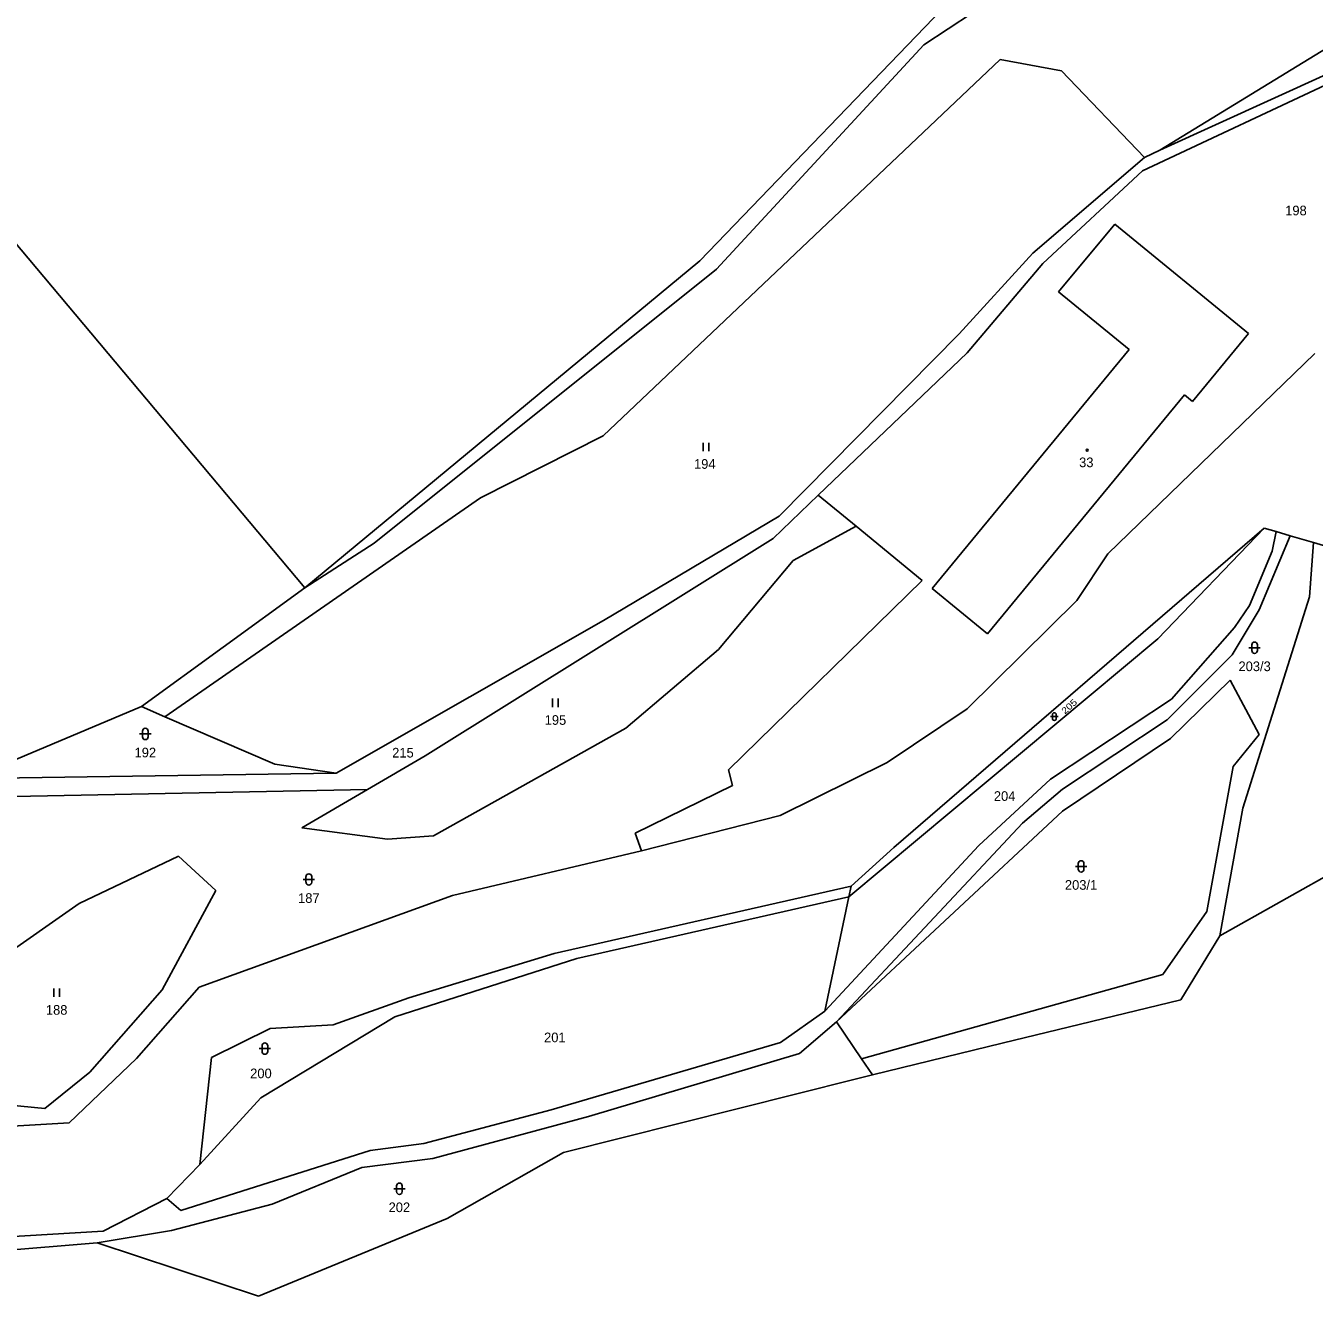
# Model space of a CAD drawing. Extents: x -601877 to -599786, y -1122905 to -1121218.
# Drawn here: x -600206.4 to -599979.4, y -1122461.1 to -1122237.3 of the extents above; entities that cross this region are included whole.
import ezdxf
from ezdxf.enums import TextEntityAlignment as Align

# ---------------------------------------------------------------- set-up
doc = ezdxf.new("R2010")
doc.units = 0
doc.header["$LTSCALE"] = 0.68
for name, color, linetype, lineweight in [('1', 7, 'Continuous', 25), ('3', 7, 'Continuous', 25), ('5', 7, 'Continuous', 25)]:
    doc.layers.add(name, color=color, linetype=linetype, lineweight=lineweight)
doc.layers.add('2', color=7, linetype='Continuous')

msp = doc.modelspace()

# ---------------------------------------------------------------- linework, layer by layer
at = {"layer": '1'}
for p, q in [((-600006.61, -1122259.26), (-599955.88, -1122228.15)), ((-600031.07, -1122229.36), (-600048.16, -1122240.69)), ((-600087.63, -1122278.73), (-600043.41, -1122232.83)), ((-600048.16, -1122240.69), (-600084.7, -1122280.19)), ((-600104.71, -1122309.54), (-600034.71, -1122243.27)), ((-600023.95, -1122245.28), (-600034.71, -1122243.27)), ((-600009.33, -1122260.51), (-600023.95, -1122245.28)), ((-599976.54, -1122245.54), (-600006.61, -1122259.26)), ((-599974.57, -1122246.46), (-600009.65, -1122262.88)), ((-600229.43, -1122250.39), (-600157.25, -1122336.33)), ((-600006.61, -1122259.26), (-600009.33, -1122260.51)), ((-600028.97, -1122277.36), (-600009.33, -1122260.51)), ((-600009.65, -1122262.88), (-600027.23, -1122279.19)), ((-600024.44, -1122284.22), (-600014.52, -1122272.3)), ((-600014.52, -1122272.3), (-599990.99, -1122291.56)), ((-600041.94, -1122291.62), (-600028.97, -1122277.36)), ((-600157.25, -1122336.33), (-600087.63, -1122278.73)), ((-600084.7, -1122280.19), (-600145.01, -1122328.47)), ((-600040.57, -1122294.91), (-600027.23, -1122279.19)), ((-600011.99, -1122294.36), (-600024.44, -1122284.22)), ((-600073.65, -1122323.71), (-600041.94, -1122291.62)), ((-599990.99, -1122291.56), (-600000.86, -1122303.54)), ((-600066.8, -1122320.02), (-600040.57, -1122294.91)), ((-600046.7, -1122336.48), (-600011.99, -1122294.36)), ((-599979.3, -1122295.06), (-600015.75, -1122330.35)), ((-600002.25, -1122302.34), (-600036.98, -1122344.44)), ((-600000.86, -1122303.54), (-600002.25, -1122302.34)), ((-600126.28, -1122320.51), (-600104.71, -1122309.54)), ((-600181.91, -1122359.05), (-600126.28, -1122320.51)), ((-600074.75, -1122327.64), (-600066.8, -1122320.02)), ((-600060.12, -1122325.49), (-600066.8, -1122320.02)), ((-600104.62, -1122342.09), (-600073.65, -1122323.71)), ((-600071.18, -1122331.55), (-600060.12, -1122325.49)), ((-600048.46, -1122335.04), (-600060.12, -1122325.49)), ((-600053.48, -1122382.07), (-599988.25, -1122325.82)), ((-599988.25, -1122325.82), (-600006.95, -1122345.31)), ((-599986.13, -1122326.44), (-599988.25, -1122325.82)), ((-600074.75, -1122327.64), (-600136.02, -1122365.94)), ((-599989.13, -1122340.24), (-599983.63, -1122327.17)), ((-599986.82, -1122329.9), (-599986.13, -1122326.44)), ((-599983.63, -1122327.17), (-599986.13, -1122326.44)), ((-599979.5, -1122328.38), (-599983.63, -1122327.17)), ((-600145.01, -1122328.47), (-600157.25, -1122336.33)), ((-600015.75, -1122330.35), (-600021.22, -1122338.56)), ((-599990.78, -1122339.47), (-599986.82, -1122329.9)), ((-599980.22, -1122337.93), (-599979.5, -1122328.38)), ((-599967.79, -1122331.82), (-599979.5, -1122328.38)), ((-600084.38, -1122347.18), (-600071.18, -1122331.55)), ((-600157.25, -1122336.33), (-600186.03, -1122357.27)), ((-600048.46, -1122335.04), (-600082.6, -1122368.42)), ((-600036.98, -1122344.44), (-600046.7, -1122336.48)), ((-600040.57, -1122357.63), (-600021.22, -1122338.56)), ((-599991.99, -1122375.13), (-599980.22, -1122337.93)), ((-599993.86, -1122348.17), (-599989.13, -1122340.24)), ((-599993.42, -1122343.32), (-599990.78, -1122339.47)), ((-600151.7, -1122368.97), (-600104.62, -1122342.09)), ((-600004.53, -1122355.98), (-599993.42, -1122343.32)), ((-600061.4, -1122390.77), (-600006.95, -1122345.31)), ((-600100.66, -1122361.04), (-600084.38, -1122347.18)), ((-600005.3, -1122359.61), (-599993.86, -1122348.17)), ((-600004.75, -1122362.86), (-599994.19, -1122352.62)), ((-599994.19, -1122352.62), (-599989.13, -1122362.15)), ((-600216.26, -1122369.96), (-600186.03, -1122357.27)), ((-600186.03, -1122357.27), (-600181.91, -1122359.05)), ((-600025.87, -1122370.07), (-600004.53, -1122355.98)), ((-600181.91, -1122359.05), (-600162.55, -1122367.41)), ((-600054.64, -1122367.14), (-600040.57, -1122357.63)), ((-600023.78, -1122371.83), (-600005.3, -1122359.61)), ((-600134.59, -1122380.03), (-600100.66, -1122361.04)), ((-599989.13, -1122362.15), (-599993.7, -1122367.81)), ((-600023.78, -1122375.68), (-600004.75, -1122362.86)), ((-600136.02, -1122365.94), (-600146.19, -1122371.89)), ((-600216.26, -1122369.96), (-600151.7, -1122368.97)), ((-600162.55, -1122367.41), (-600151.7, -1122368.97)), ((-600082.6, -1122368.42), (-600081.87, -1122371.16)), ((-600073.47, -1122376.47), (-600054.64, -1122367.14)), ((-599993.7, -1122367.81), (-599998.32, -1122393.35)), ((-600081.87, -1122371.16), (-600099.05, -1122379.57)), ((-600038.52, -1122381.74), (-600025.87, -1122370.07)), ((-600215.93, -1122373.26), (-600146.19, -1122371.89)), ((-600146.19, -1122371.89), (-600157.75, -1122378.65)), ((-600030.82, -1122377.77), (-600023.78, -1122371.83)), ((-600063.59, -1122412.77), (-600023.78, -1122375.68)), ((-599996.04, -1122397.64), (-599991.99, -1122375.13)), ((-600097.95, -1122382.68), (-600073.47, -1122376.47)), ((-600063.59, -1122412.77), (-600030.82, -1122377.77)), ((-600157.75, -1122378.65), (-600142.68, -1122380.64)), ((-600142.68, -1122380.64), (-600134.59, -1122380.03)), ((-600099.05, -1122379.57), (-600097.95, -1122382.68)), ((-600065.63, -1122410.9), (-600038.52, -1122381.74)), ((-600061.01, -1122388.89), (-600053.48, -1122382.07)), ((-600179.52, -1122383.61), (-600197.01, -1122391.97)), ((-600172.92, -1122389.66), (-600179.52, -1122383.61)), ((-600131.24, -1122390.54), (-600097.95, -1122382.68)), ((-599996.04, -1122397.64), (-599974.31, -1122385.44)), ((-600113.31, -1122400.78), (-600061.01, -1122388.89)), ((-600061.4, -1122390.77), (-600061.01, -1122388.89)), ((-600182.38, -1122407.16), (-600172.92, -1122389.66)), ((-600175.89, -1122406.72), (-600131.24, -1122390.54)), ((-600109.35, -1122401.66), (-600061.4, -1122390.77)), ((-600065.63, -1122410.9), (-600061.4, -1122390.77)), ((-600197.01, -1122391.97), (-600221.65, -1122409.14)), ((-599998.32, -1122393.35), (-600006.07, -1122404.46)), ((-600002.93, -1122408.92), (-599996.04, -1122397.64)), ((-600141.36, -1122411.89), (-600109.35, -1122401.66)), ((-600138.94, -1122408.59), (-600113.31, -1122400.78)), ((-600195.14, -1122421.69), (-600182.38, -1122407.16)), ((-600186.89, -1122419.27), (-600175.89, -1122406.72)), ((-600152.25, -1122413.32), (-600138.94, -1122408.59)), ((-600034.4, -1122416.58), (-600002.93, -1122408.92)), ((-600165, -1122426.2), (-600141.36, -1122411.89)), ((-600073.44, -1122416.46), (-600065.63, -1122410.9)), ((-600173.69, -1122419.1), (-600163.35, -1122413.99)), ((-600163.35, -1122413.99), (-600152.25, -1122413.32)), ((-600070.08, -1122418.39), (-600063.59, -1122412.77)), ((-600063.59, -1122412.77), (-600059.15, -1122419.34)), ((-600113.86, -1122428.29), (-600073.44, -1122416.46)), ((-600057.25, -1122422.14), (-600034.4, -1122416.58)), ((-600107.26, -1122429.5), (-600070.08, -1122418.39)), ((-600198.77, -1122430.6), (-600186.89, -1122419.27)), ((-600175.73, -1122437.92), (-600173.69, -1122419.1)), ((-600203.06, -1122428.07), (-600195.14, -1122421.69)), ((-600111.68, -1122435.81), (-600060.28, -1122422.88)), ((-600060.28, -1122422.88), (-600057.25, -1122422.14)), ((-600230.94, -1122425.27), (-600203.06, -1122428.07)), ((-600175.73, -1122437.92), (-600165, -1122426.2)), ((-600136.3, -1122434.24), (-600113.86, -1122428.29)), ((-600134.7, -1122436.88), (-600107.26, -1122429.5)), ((-600209.77, -1122431.26), (-600198.77, -1122430.6)), ((-600145.76, -1122435.45), (-600136.3, -1122434.24)), ((-600179.08, -1122446.01), (-600145.76, -1122435.45)), ((-600147.19, -1122438.47), (-600134.7, -1122436.88)), ((-600132.18, -1122447.43), (-600111.68, -1122435.81)), ((-600181.56, -1122443.92), (-600175.73, -1122437.92)), ((-600163.02, -1122444.91), (-600147.19, -1122438.47)), ((-600192.78, -1122449.7), (-600181.56, -1122443.92)), ((-600181.56, -1122443.92), (-600179.08, -1122446.01)), ((-600180.73, -1122449.54), (-600163.02, -1122444.91)), ((-600165.41, -1122461.14), (-600132.18, -1122447.43)), ((-600219.61, -1122451.24), (-600192.78, -1122449.7)), ((-600193.84, -1122451.72), (-600180.73, -1122449.54)), ((-600218.47, -1122453.82), (-600193.84, -1122451.72)), ((-600193.84, -1122451.72), (-600165.41, -1122461.14))]:
    msp.add_line(p, q, dxfattribs=at)
msp.add_lwpolyline([(-600006.07, -1122404.46), (-600059.15, -1122419.34), (-600057.25, -1122422.14)], dxfattribs=at)
at = {"layer": '3'}
for p, q in [((-600087.071, -1122312.29), (-600087.071, -1122310.79)), ((-600086.07, -1122312.29), (-600086.07, -1122310.79)), ((-599990.901, -1122346.891), (-599988.899, -1122346.891)), ((-599990.401, -1122346.391), (-599990.401, -1122347.392)), ((-599989.399, -1122347.392), (-599989.399, -1122346.391)), ((-600113.601, -1122357.35), (-600113.601, -1122355.85)), ((-600112.6, -1122357.35), (-600112.6, -1122355.85)), ((-600025.861, -1122359.031), (-600024.519, -1122359.031)), ((-600025.525, -1122358.695), (-600025.525, -1122359.366)), ((-600024.855, -1122359.366), (-600024.855, -1122358.695)), ((-600186.351, -1122362.081), (-600184.349, -1122362.081)), ((-600185.851, -1122361.581), (-600185.851, -1122362.582)), ((-600184.849, -1122362.582), (-600184.849, -1122361.581)), ((-600021.481, -1122385.411), (-600019.479, -1122385.411)), ((-600020.981, -1122384.911), (-600020.981, -1122385.912)), ((-600019.979, -1122385.912), (-600019.979, -1122384.911)), ((-600157.541, -1122387.721), (-600155.539, -1122387.721)), ((-600157.041, -1122387.221), (-600157.041, -1122388.222)), ((-600156.039, -1122388.222), (-600156.039, -1122387.221)), ((-600201.481, -1122408.42), (-600201.481, -1122406.92)), ((-600200.48, -1122408.42), (-600200.48, -1122406.92)), ((-600165.291, -1122417.521), (-600163.289, -1122417.521)), ((-600164.791, -1122417.021), (-600164.791, -1122418.022)), ((-600163.789, -1122418.022), (-600163.789, -1122417.021)), ((-600141.591, -1122442.201), (-600139.589, -1122442.201)), ((-600141.091, -1122441.701), (-600141.091, -1122442.702)), ((-600140.089, -1122442.702), (-600140.089, -1122441.701))]:
    msp.add_line(p, q, dxfattribs=at)
for centre, radius, start, end in [((-599989.9, -1122346.3909), 0.5, 0, 180), ((-599989.9, -1122347.3909), 0.5, 180, 359.98789), ((-600025.19, -1122358.6956), 0.335, 0, 180), ((-600025.19, -1122359.3656), 0.335, 180, 359.98789), ((-600185.35, -1122361.5809), 0.5, 0, 180), ((-600185.35, -1122362.5809), 0.5, 180, 359.98789), ((-600020.48, -1122384.9109), 0.5, 0, 180), ((-600156.54, -1122387.2209), 0.5, 0, 180), ((-600020.48, -1122385.9109), 0.5, 180, 359.98789), ((-600156.54, -1122388.2209), 0.5, 180, 359.98789), ((-600164.29, -1122417.0209), 0.5, 0, 180), ((-600164.29, -1122418.0209), 0.5, 180, 359.98789), ((-600140.59, -1122441.7009), 0.5, 0, 180), ((-600140.59, -1122442.7009), 0.5, 180, 359.98789)]:
    msp.add_arc(centre, radius, start, end, dxfattribs=at)
at = {"layer": '5'}
msp.add_circle((-600019.3868, -1122312.0992), 0.175, dxfattribs=at)

# ---------------------------------------------------------------- texts
at = {"layer": '2'}
for s, p in [('198', (-599982.619, -1122270.715)), ('194', (-600086.779, -1122315.365)), ('33', (-600019.559, -1122315.085)), ('203/3', (-599989.9, -1122351.015)), ('195', (-600113.089, -1122360.475)), ('192', (-600185.349, -1122366.205)), ('215', (-600139.959, -1122366.235)), ('204', (-600033.949, -1122373.875)), ('203/1', (-600020.48, -1122389.535)), ('187', (-600156.539, -1122391.845)), ('188', (-600200.969, -1122411.545)), ('201', (-600113.199, -1122416.395)), ('200', (-600164.979, -1122422.735)), ('202', (-600140.589, -1122446.325))]:
    msp.add_text(s, height=1.7, dxfattribs=at).set_placement(p, align=Align.CENTER)
at = {"layer": '2', "width": 1.2}
msp.add_text('205', height=1.14, rotation=42, dxfattribs=at).set_placement((-600022.1844, -1122357.6666), align=Align.CENTER)

doc.saveas('drawing.dxf')
